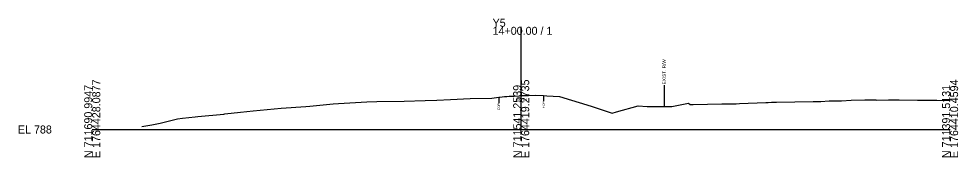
# Model space of a CAD drawing. Extents: x -26 to 303, y -10 to 4039.
# Drawn here: x -25.7 to 302.8, y 3990.3 to 4038.7 of the extents above; entities that cross this region are included whole.
import ezdxf

# ---------------------------------------------------------------- set-up
doc = ezdxf.new("R2010")
doc.units = 0
for name, color, linetype in [('Default', 7, 'Continuous'), ('Exist Cross Section Cell', 7, 'Continuous'), ('Exist XS Center Line Elevation Label', 7, 'Continuous'), ('Exist XS Ground Line', 7, 'Continuous'), ('Old_Level_10', 7, 'Continuous')]:
    doc.layers.add(name, color=color, linetype=linetype)

msp = doc.modelspace()

# ---------------------------------------------------------------- linework, layer by layer
at = {"layer": 'Exist Cross Section Cell'}
for p, q in [((150, 4000), (150, 4035.92)), ((0, 4000), (150, 4000)), ((150, 4000), (300, 4000))]:
    msp.add_line(p, q, dxfattribs=at)
at = {"layer": 'Exist XS Ground Line'}
msp.add_lwpolyline([(17.37, 4001.08), (20.83, 4001.63), (23.76, 4002.19), (29.77, 4003.78), (31.6, 4004.02), (36.01, 4004.48), (36.89, 4004.58), (46.03, 4005.41), (46.35, 4005.46), (51.89, 4006.07), (56.31, 4006.55), (66.07, 4007.43), (74.74, 4008.06), (76.08, 4008.18), (84.2, 4008.96), (86.1, 4009.04), (96.05, 4009.66), (99.52, 4009.78), (109.08, 4009.96), (116.38, 4010.15), (120.49, 4010.31), (125.3, 4010.54), (132.11, 4010.89), (139.77, 4011.01), (142.15, 4011.3), (142.5, 4011.36), (144.18, 4011.49), (145, 4011.55), (145.77, 4011.6), (147.5, 4011.71), (149.45, 4011.81), (150, 4011.84), (152.11, 4011.9), (152.51, 4011.91), (155.12, 4011.97), (157.86, 4011.93), (159.03, 4011.77), (163.41, 4011.5), (174.44, 4008.11), (181.86, 4005.77), (183.31, 4006.21), (190.91, 4008.3), (194.08, 4008.03), (200.95, 4008.09), (202.67, 4008.05), (208.52, 4009.24), (209.05, 4008.75), (210.12, 4008.8), (220.16, 4008.96), (225.16, 4009.03), (226.36, 4009.07), (235.59, 4009.49), (236.38, 4009.5), (237.54, 4009.51), (238.06, 4009.55), (239.31, 4009.58), (252.06, 4009.78), (254.76, 4009.82), (257.7, 4009.98), (261.67, 4010.02), (262.02, 4010.02), (265.46, 4010.23), (270.19, 4010.34), (272.41, 4010.33), (274.02, 4010.32), (274.34, 4010.31), (278.44, 4010.35), (282.2, 4010.33), (288.58, 4010.31), (295.37, 4010.28), (300, 4010.15)], dxfattribs=at)
at = {"layer": 'Old_Level_10'}
for p, q in [((199.99, 4015.48), (199.99, 4008.08)), ((157.86, 4011.93), (157.86, 4009.88)), ((142.15, 4011.3), (142.15, 4009.25))]:
    msp.add_line(p, q, dxfattribs=at)

# ---------------------------------------------------------------- texts
at = {"layer": 'Default'}
msp.add_text('-', height=0.0001, dxfattribs=at).set_placement((0, 4000))
at = {"layer": 'Exist Cross Section Cell'}
for s, p in [('Y5', (140, 4035.92)), ('14+00.00 / 1', (140, 4033.12)), ('EL 788', (-26, 3998.6))]:
    msp.add_text(s, height=2.8, dxfattribs=at).set_placement(p)
for s, p in [('N 711690.9947', (0, 3990)), ('E 1764428.0877', (2.8, 3990)), ('N 711541.2539', (150, 3990)), ('E 1764419.2735', (152.8, 3990)), ('N 711391.5131', (300, 3990)), ('E 1764410.4594', (302.8, 3990))]:
    msp.add_text(s, height=2.8, rotation=90, dxfattribs=at).set_placement(p)
at = {"layer": 'Exist XS Center Line Elevation Label'}
msp.add_text('799.84', height=1, dxfattribs=at).set_placement((147.86, 4009.84))
at = {"layer": 'Old_Level_10'}
for s, height, p in [('EXIST. R/W', 1.181, (200.58, 4015.78)), ('EOP', 0.787, (142.54, 4006.85)), ('EOP', 0.787, (158.25, 4007.48))]:
    msp.add_text(s, height=height, rotation=90, dxfattribs=at).set_placement(p)

doc.saveas('drawing.dxf')
